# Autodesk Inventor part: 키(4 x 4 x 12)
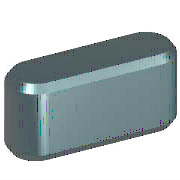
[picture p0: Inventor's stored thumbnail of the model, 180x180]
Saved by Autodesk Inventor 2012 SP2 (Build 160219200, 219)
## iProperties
IsCustomPart: 0
Created: 2009-02
Part Number: 키(4 x 4 x 12)
Material: 강, 연강
Description: 키 및 해당 키홈
Document SubType Name: Modeling
Standard: KS B 1311
Designer: KYOUNG IL JANG
Standards Organization: KS
Language: ko-KR
Size Designation: 4 x 4 x 12
Categories: <MemberInstance><Categories><Category DisplayName="샤프트 부품" InternalName="7f7aeb1f-a693-4053-b835-cee3144e0d98" Mnemonic="SHFT"><Category DisplayName="키" Interna
Density: 7.86 g/cm^3
Mass: 1.38739 g
Surface Area: 1.94869 cm^2
Volume: 0.176513 cm^3
Author: KYOUNG IL JANG
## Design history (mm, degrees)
workplane "Work Plane1"
workplane "Work Plane2"
sketch "스케치1"
  geometry: L1 (2, 2)-(10, 2); L2 (10, -2)-(2, -2); L3 (0, 9.4)-(0, -7.4) reference; L4 (-5, 0)-(30, 0) reference; L5 (12, 0)-(12, 7); A1 r 2 centre (2, 0) between (2, 2) and (2, -2); A2 r 2 centre (10, 0) between (10, -2) and (10, 2)
  constraints: 6 end point, 5 point on circle, 4 tangent, 3 point on line, 2 centre point, 1 horizontal, 1 parallel, 1 perpendicular
  dimensions: "d0" = 2 radius of A1 (= 0.5 x PB); "d13" = 2 radius of A2 (= 0.5 x PB); "d14" = 12 distance between parallel lines of L5 L3 (= NLG)
extrude "본체1" new body sketch "스케치1" taper "d3" = 0 deg; stored distance "d4" = 10
workplane "Work Plane3"
body "Solid1"
chamfer "모따기1" distance "d8" = 0.25 (= PHH); stored, may be unused: second distance "d9" = 0.25 (= PHH), angle "d15" = 45 deg
other parameters: "d1" = -2.5 (= -PNT), "d2" = 1.5 (= PH - PNT), "NLG" = 12 [user parameter; used in 3 equation terms], "PB" = 4 [user parameter; used in 2 equation terms], "PNT" = 2.5 [user parameter; used in 2 equation terms], "PH" = 4 [user parameter; used in 1 equation term], "PHH" = 0.25 [user parameter; used in 2 equation terms], "d10" = 0, "d16" = 0, "d17" = 0, "d18" = 0, "PLB2" = 12 (= NLG) [user parameter], "WDMAX" = 12 [user parameter], "PLB1" = 12 (= NLG) [user parameter], "RR" = 0.08 [user parameter], "PUEB" = 1.8 [user parameter]
